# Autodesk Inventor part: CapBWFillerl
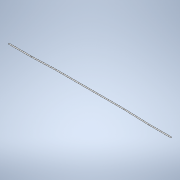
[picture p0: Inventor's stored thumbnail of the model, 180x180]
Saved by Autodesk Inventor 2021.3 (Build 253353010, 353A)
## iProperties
Created: 2021-11
Part Number: CapBWFillerl
Material: Polystyrene, High Impact
Document SubType Name: Modeling
Designer: u1426
Density: 1.022 g/cm^3
Appearance: Smooth - White
Author: u1426
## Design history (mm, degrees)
sketch "Sketch1"
  geometry: L1 (5486.4, 0)-(3962.4, 0); L2 (-5486.4, 0)-(-3962.4, 0); L3 (-3962.4, 0)-(-2336.8, 60.96); L4 (-2336.8, 60.96)-(2336.8, 60.96); L5 (2336.8, 60.96)-(3962.4, 0); L6 (5486.4, 6.35)-(3962.519, 6.35); L7 (3962.519, 6.35)-(2336.919, 67.31); L8 (2336.919, 67.31)-(-2336.919, 67.31); L9 (-2336.919, 67.31)-(-3962.519, 6.35); L10 (-3962.519, 6.35)-(-5486.4, 6.35); L11 (5486.4, 0)-(5486.4, 6.35); L12 (-5486.4, 0)-(-5486.4, 6.35); 1 further point
  constraints: 24 end point, 2 collinear, 2 horizontal, 2 vertical, 4 other
  dimensions: "d4" = 1524 distance of L1.start L1.end; "d5" = 1524 distance of L2.start L2.end; "d6" = 1625.6 horizontal distance of L4.end L1.end; "d7" = 1625.6 horizontal distance of L2.end L3.end; "d8" = 4673.6 distance of L3.end L4.end (derived); "d9" = 2336.8 horizontal distance of L3.end point (0, 0) (derived); "d10" = 60.96 vertical distance of L2.end L3.end; "d51" = 6.35 distance between parallel lines of L4 L8; "d52" = 5486.4 distance from line of L12 point (0, 0); "d53" = 0 distance from line of L2 point (0, 0)
extrude "Extrusion1" new body sketch "Sketch1" distance "d11" = 76.2; taper "d12" = 0 deg
body "Solid1"
